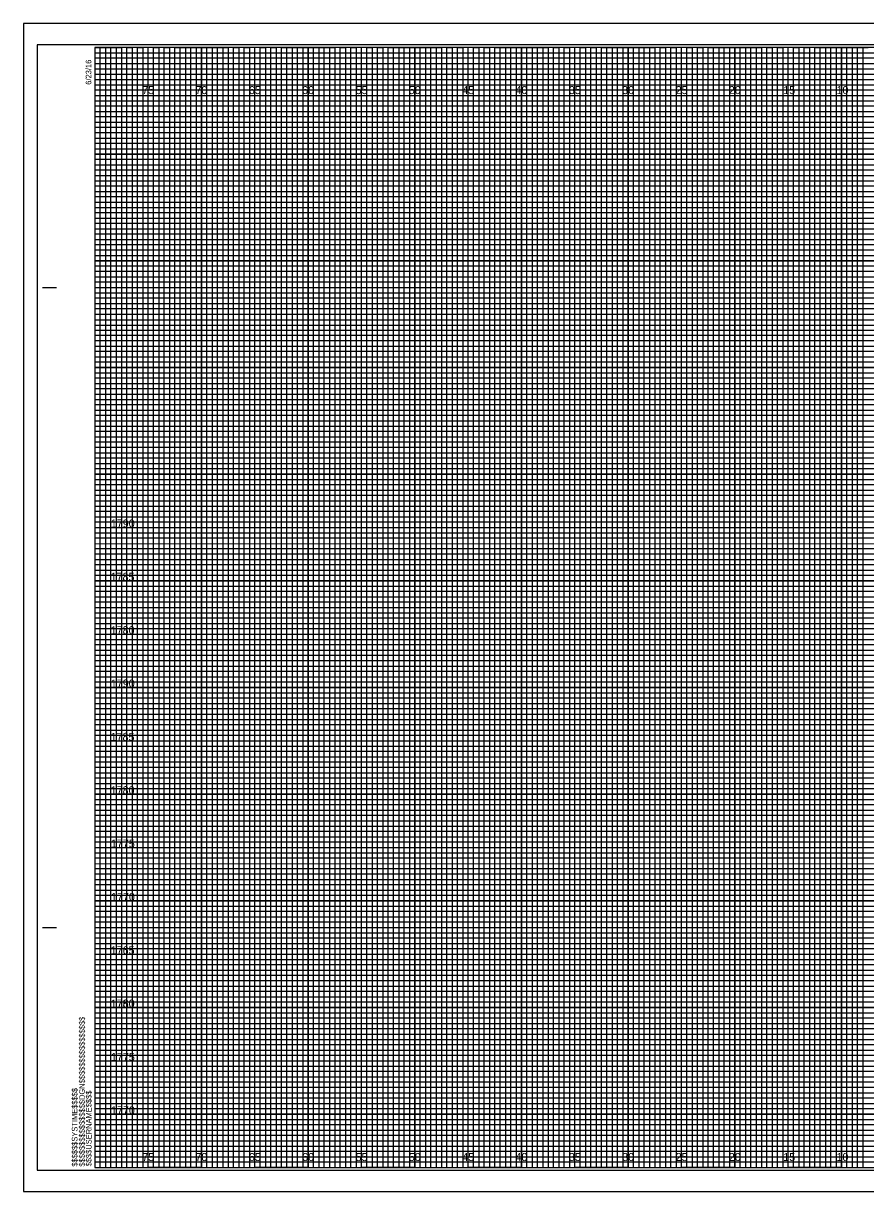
# Model space of a CAD drawing. Extents: x -7 to 162, y -2 to 107.
# Drawn here: x -6.7 to 72.2, y -2.3 to 107.3 of the extents above; entities that cross this region are included whole.
import ezdxf

# ---------------------------------------------------------------- set-up
doc = ezdxf.new("R2010")
doc.units = 0
for name, color, linetype in [('Prop XS Elevation Labels', 7, 'Continuous'), ('Prop XS Offset Labels', 7, 'Continuous'), ('Sheet Cross Section CELL', 7, 'Continuous'), ('Sheet Cross Section Grid Major CELL', 7, 'Continuous'), ('Sheet Cross Section Grid Middle CELL', 7, 'Continuous'), ('Sheet Cross Section Grid Minor 1 CELL', 7, 'Continuous'), ('Sheet Cross Section Grid Minor 2 CELL', 7, 'Continuous'), ('Sheet Cutting Line CELL', 7, 'Continuous'), ('Sheet DOT Grid CELL', 7, 'Continuous'), ('Sheet Plot Border Inside CELL', 7, 'Continuous'), ('Sheet Plot Border Outside CELL', 7, 'Continuous')]:
    doc.layers.add(name, color=color, linetype=linetype)

msp = doc.modelspace()

# ---------------------------------------------------------------- linework, layer by layer
at = {"layer": 'Sheet Cross Section CELL'}
for p, q in [((-4.9, 82.5), (-3.65, 82.5)), ((-4.85, 82.5), (-3.6, 82.5)), ((-4.9, 22.5), (-3.65, 22.5)), ((-4.85, 22.5), (-3.6, 22.5)), ((0, 0), (0, 0)), ((0, 0), (0, 0)), ((0, 0), (0, 0)), ((0, 0), (0, 0)), ((0, 0), (0, 0)), ((0, 0), (0, 0)), ((0, 0), (0, 0))]:
    msp.add_line(p, q, dxfattribs=at)
msp.add_lwpolyline([(160, 105), (0, 105), (0, 0), (160, 0)], close=True, dxfattribs=at)
at = {"layer": 'Sheet Cross Section Grid Major CELL'}
for p, q in [((5, 105), (0, 105)), ((5, 0), (5, 105)), ((15, 105), (10, 105)), ((10, 105), (10, 0)), ((15, 0), (15, 105)), ((25, 105), (20, 105)), ((20, 105), (20, 0)), ((25, 0), (25, 105)), ((35, 105), (30, 105)), ((30, 105), (30, 0)), ((35, 0), (35, 105)), ((45, 105), (40, 105)), ((40, 105), (40, 0)), ((45, 0), (45, 105)), ((55, 105), (50, 105)), ((50, 105), (50, 0)), ((55, 0), (55, 105)), ((65, 105), (60, 105)), ((60, 105), (60, 0)), ((65, 0), (65, 105)), ((75, 105), (70, 105)), ((70, 105), (70, 0)), ((10, 0), (5, 0)), ((20, 0), (15, 0)), ((30, 0), (25, 0)), ((40, 0), (35, 0)), ((50, 0), (45, 0)), ((60, 0), (55, 0)), ((70, 0), (65, 0))]:
    msp.add_line(p, q, dxfattribs=at)
for points in [[(0, 100), (160, 100), (160, 95), (0, 95)], [(0, 90), (160, 90), (160, 85), (0, 85)], [(0, 80), (160, 80), (160, 75), (0, 75)], [(0, 70), (160, 70), (160, 65), (0, 65)], [(0, 60), (160, 60), (160, 55), (0, 55)], [(0, 50), (160, 50), (160, 45), (0, 45)], [(0, 40), (160, 40), (160, 35), (0, 35)], [(0, 30), (160, 30), (160, 25), (0, 25)], [(0, 20), (160, 20), (160, 15), (0, 15)], [(0, 10), (160, 10), (160, 5), (0, 5)]]:
    msp.add_lwpolyline(points, dxfattribs=at)
at = {"layer": 'Sheet Cross Section Grid Middle CELL'}
for points in [[(0, 105), (2.5, 105), (2.5, 0), (7.5, 0), (7.5, 105), (12.5, 105), (12.5, 0), (17.5, 0), (17.5, 105), (22.5, 105), (22.5, 0), (27.5, 0), (27.5, 105), (32.5, 105), (32.5, 0), (37.5, 0), (37.5, 105), (42.5, 105), (42.5, 0), (47.5, 0), (47.5, 105), (52.5, 105), (52.5, 0), (57.5, 0), (57.5, 105), (62.5, 105), (62.5, 0), (67.5, 0), (67.5, 105), (72.5, 105)], [(0, 102.5), (137.5, 102.5)], [(0, 92.5), (160, 92.5), (160, 97.5), (0, 97.5)], [(0, 82.5), (160, 82.5), (160, 87.5), (0, 87.5)], [(0, 72.5), (160, 72.5), (160, 77.5), (0, 77.5)], [(0, 62.5), (160, 62.5), (160, 67.5), (0, 67.5)], [(0, 52.5), (160, 52.5), (160, 57.5), (0, 57.5)], [(0, 42.5), (160, 42.5), (160, 47.5), (0, 47.5)], [(0, 32.5), (160, 32.5), (160, 37.5), (0, 37.5)], [(0, 22.5), (160, 22.5), (160, 27.5), (0, 27.5)], [(0, 12.5), (160, 12.5), (160, 17.5), (0, 17.5)], [(0, 2.5), (160, 2.5), (160, 7.5), (0, 7.5)]]:
    msp.add_lwpolyline(points, dxfattribs=at)
at = {"layer": 'Sheet Cross Section Grid Minor 1 CELL'}
for p, q in [((0, 104.5), (130, 104.5)), ((130, 103.99), (0, 103.99)), ((0, 103.99), (0, 103.5)), ((0, 103.5), (130, 103.5)), ((130, 102.95), (0, 102.95)), ((0, 102.95), (0, 102)), ((0, 102), (160, 102))]:
    msp.add_line(p, q, dxfattribs=at)
for points in [[(0, 101.5), (135, 101.5), (160, 101.5), (160, 101), (0, 101)], [(0, 100.5), (160, 100.5), (160, 99.5), (0, 99.5)], [(0, 99), (160, 99), (160, 98.5), (0, 98.49)], [(0, 98), (160, 98), (160, 97), (0, 97)], [(0, 96.5), (160, 96.5), (160, 96), (0, 96)], [(0, 95.5), (160, 95.5), (160, 94.5), (0, 94.5)], [(0, 94), (160, 94), (160, 93.5), (0, 93.5)], [(0, 93), (160, 93), (160, 92), (0, 92)], [(0, 91.5), (160, 91.5), (160, 91), (0, 91)], [(0, 90.5), (160, 90.5), (160, 89.5), (0, 89.5)], [(0, 89), (160, 89), (160, 88.5), (0, 88.5)], [(0, 88), (160, 88), (160, 86.98), (160, 86.5), (160, 86), (0, 86)], [(0, 87), (160, 87), (160, 86.5), (0, 86.5)], [(0, 85.5), (160, 85.5), (160, 84.5), (0, 84.52)], [(0, 84.52), (160, 84.5), (160, 84), (0, 84)], [(0, 83.5), (160, 83.5), (160, 83), (0, 83)], [(0, 82), (160, 82), (160, 81.5), (0, 81.5)], [(0, 81), (160, 81), (160, 80.5), (0, 80.5)], [(-0.04, 79.45), (160, 79.45), (160, 78.94), (-0.04, 78.94)], [(0, 78.5), (160, 78.5), (160, 78), (0, 78)], [(0, 77), (160, 77), (160, 76.5), (0, 76.5)], [(0, 76), (160, 76), (160, 75.5), (0, 75.5)], [(0, 74.5), (160, 74.5), (160, 74), (0, 74)], [(0, 73.5), (160, 73.5), (160, 73), (0, 73)], [(0, 72), (160, 72), (160, 71.5), (0, 71.5)], [(0, 71), (160, 71), (160, 70.5), (0, 70.5)], [(0, 69.5), (160, 69.5), (160, 68.99), (0, 69)], [(0, 68.5), (160, 68.5), (160, 68), (0, 68)], [(0, 67), (160, 67), (160, 66.5), (0, 66.5)], [(0, 66), (160, 66), (160, 65.5), (0, 65.5)], [(0, 64.5), (160, 64.5), (160, 64), (0, 64)], [(0, 63.5), (160, 63.5), (160, 63), (0, 63)], [(0, 62), (160, 62), (160, 61.5), (0, 61.5)], [(0, 61), (160, 61), (160, 60.5), (0, 60.5)], [(0, 59.5), (160, 59.5), (160, 59), (0, 59)], [(0, 58.5), (160.03, 58.45), (160, 58), (0, 58)], [(0, 57), (160, 57), (160, 56.5), (0, 56.5)], [(0, 56), (160, 56), (160, 55.5), (0, 55.5)], [(0, 54.5), (160, 54.5), (160, 54), (0, 54)], [(0, 53.5), (160, 53.5), (160, 53), (0, 53)], [(0, 52), (160, 52), (160, 51.5), (0, 51.5)], [(0, 51), (160, 51), (160, 50.5), (0, 50.5)], [(0, 49.5), (160, 49.5), (160, 49), (0, 49)], [(0, 48.5), (160, 48.5), (160, 48), (0, 48)], [(0, 47), (160, 47), (160, 46.5), (0, 46.5)], [(0, 46), (160, 46), (160, 45.5), (0, 45.5)], [(0, 44.5), (160, 44.5), (160, 44), (0, 44)], [(0, 43.5), (160, 43.5), (160, 43), (0, 43)], [(0, 42), (160, 42), (160, 41.5), (0, 41.5)], [(0, 41), (160, 41), (160, 40.5), (0, 40.5)], [(0, 39.5), (160, 39.5), (160, 38.99), (0, 39)], [(0, 38.5), (160, 38.5), (160, 38), (0, 38)], [(0, 37), (160, 37), (160, 36.5), (0, 36.5)], [(0, 36), (160, 36), (160, 35.5), (0, 35.5)], [(0, 34.5), (160, 34.5), (160, 34), (0, 34)], [(0, 33.5), (160, 33.5), (160, 33), (0, 33)], [(0, 32), (160, 32), (160, 31.5), (0, 31.5)], [(0, 31), (160, 31), (160, 30.5), (0, 30.5)], [(0, 29.5), (160, 29.5), (160, 29), (0, 29)], [(0, 28.5), (160.03, 28.46), (160, 28), (0, 28)], [(0, 27), (160, 27), (160, 26.5), (0, 26.5)], [(0, 26), (160, 26), (160, 25.5), (0, 25.5)], [(0, 24.5), (160, 24.5), (160, 24), (0, 24)], [(0, 23.5), (160, 23.5), (160, 23), (0, 23)], [(0, 22), (160, 22), (160, 21.5), (0, 21.5)], [(0, 21), (160, 21), (160, 20.5), (0, 20.5)], [(0, 19.5), (160, 19.5), (160, 19), (0, 19)], [(0, 18.5), (160, 18.5), (160, 18), (0, 18)], [(0, 17), (160, 17), (160, 16.5), (0, 16.5)], [(0, 16), (160, 16), (160, 15.5), (0, 15.5)], [(0, 14.5), (160, 14.5), (160, 14), (0, 14)], [(0, 13.5), (160, 13.5), (160, 13), (0, 13)], [(0, 12), (160, 12), (160, 11.5), (0, 11.5)], [(0, 11), (160, 11), (160, 10.5), (0, 10.5)], [(0, 9.5), (160, 9.5), (160, 9), (0, 9)], [(0, 8.5), (160, 8.5), (160, 8), (0, 8)], [(0, 7), (160, 7), (160, 6.5), (0, 6.5)], [(0, 6), (160, 6), (160, 5.5), (0, 5.5)], [(0, 4.5), (160, 4.5), (160, 4), (0, 4)], [(0, 3.5), (160, 3.5), (160, 3), (0, 3)], [(0, 2), (160, 2), (160, 1.5), (0, 1.5)], [(0, 1), (160, 1), (160, 0.5), (0, 0.5)]]:
    msp.add_lwpolyline(points, dxfattribs=at)
at = {"layer": 'Sheet Cross Section Grid Minor 2 CELL'}
for points in [[(0, 0), (0.5, 0), (0.5, 105), (1, 105), (1, 0)], [(1, 0), (1.5, 0), (1.5, 105), (2, 105), (2, 0)], [(2.5, 0), (3, 0), (3, 105), (3.5, 105), (3.5, 0)], [(3.5, 0), (4, 0), (4, 105), (4.5, 105), (4.5, 0)], [(5, 0), (5.5, 0), (5.5, 105), (6, 105), (6, 0)], [(6, 0), (6.5, 0), (6.5, 105), (7, 105), (7, 0)], [(7.5, 0), (8, 0), (8, 105), (8.5, 105), (8.5, 0)], [(8.5, 0), (9, 0), (9, 105), (9.5, 105), (9.5, 0)], [(10, 0), (10.5, 0), (10.5, 105), (11, 105), (11, 0)], [(11, 0), (11.5, 0), (11.5, 105), (12, 105), (12, 0)], [(12.5, 0), (13, 0), (13, 105), (13.5, 105), (13.5, 0)], [(13.5, 0), (14, 0), (14, 105), (14.5, 105), (14.5, 0)], [(15, 0), (15.5, 0), (15.5, 105), (16, 105), (16, 0)], [(16, 0), (16.5, 0), (16.5, 105), (17, 105), (17, 0)], [(17.5, 0), (18, 0), (18, 105), (18.5, 105), (18.5, 0)], [(18.5, 0), (19, 0), (19, 105), (19.5, 105), (19.5, 0)], [(20, 0), (20.5, 0), (20.5, 105), (21, 105), (21, 0)], [(21, 0), (21.5, 0), (21.5, 105), (22, 105), (22, 0)], [(22.5, 0), (23, 0), (23, 105), (23.5, 105), (23.5, 0)], [(23.5, 0), (24, 0), (24, 105), (24.5, 105), (24.5, 0)], [(25, 0), (25.5, 0), (25.5, 105), (26, 105), (26, 0)], [(26, 0), (26.5, 0), (26.5, 105), (27, 105), (27, 0)], [(27.5, 0), (28, 0), (28, 105), (28.5, 105), (28.5, 0)], [(28.5, 0), (29, 0), (29, 105), (29.5, 105), (29.5, 0)], [(30, 0), (30.5, 0), (30.5, 105), (31, 105), (31, 0)], [(31, 0), (31.5, 0), (31.5, 105), (32, 105), (32, 0)], [(32.5, 0), (33, 0), (33, 105), (33.5, 105), (33.5, 0)], [(33.5, 0), (34, 0), (34, 105), (34.5, 105), (34.5, 0)], [(35, 0), (35.5, 0), (35.5, 105), (36, 105), (36, 0)], [(36, 0), (36.5, 0), (36.5, 105), (37, 105), (37, 0)], [(37.5, 0), (38, 0), (38, 105), (38.5, 105), (38.5, 0)], [(38.5, 0), (39, 0), (39, 105), (39.5, 105), (39.5, 0)], [(40, 0), (40.5, 0), (40.5, 105), (41, 105), (41, 0)], [(41, 0), (41.5, 0), (41.5, 105), (42, 105), (42, 0)], [(42.5, 0), (43, 0), (43, 105), (43.5, 105), (43.5, 0)], [(43.5, 0), (44, 0), (44, 105), (44.5, 105), (44.5, 0)], [(45, 0), (45.5, 0), (45.5, 105), (46, 105), (46, 0)], [(46, 0), (46.5, 0), (46.5, 105), (47, 105), (47, 0)], [(47.5, 0), (48, 0), (48, 105), (48.5, 105), (48.5, 0)], [(48.5, 0), (49, 0), (49, 105), (49.5, 105), (49.5, 0)], [(50, 0), (50.5, 0), (50.5, 105), (51, 105), (51, 0)], [(51, 0), (51.5, 0), (51.5, 105), (52, 105), (52, 0)], [(52.5, 0), (53, 0), (53, 105), (53.5, 105), (53.5, 0)], [(53.5, 0), (54, 0), (54, 105), (54.5, 105), (54.5, 0)], [(55, 0), (55.5, 0), (55.5, 105), (56, 105), (56, 0)], [(56, 0), (56.5, 0), (56.5, 105), (57, 105), (57, 0)], [(57.5, 0), (58, 0), (58, 105), (58.5, 105), (58.5, 0)], [(58.5, 0), (59, 0), (59, 105), (59.5, 105), (59.5, 0)], [(60, 0), (60.5, 0), (60.5, 105), (61, 105), (61, 0)], [(61, 0), (61.5, 0), (61.5, 105), (62, 105), (62, 0)], [(62.5, 0), (63, 0), (63, 105), (63.5, 105), (63.5, 0)], [(63.5, 0), (64, 0), (64, 105), (64.5, 105), (64.5, 0)], [(65, 0), (65.5, 0), (65.5, 105), (66, 105), (66, 0)], [(66, 0), (66.5, 0), (66.5, 105), (67, 105), (67, 0)], [(67.5, 0), (68, 0), (68, 105), (68.5, 105), (68.5, 0)], [(68.5, 0), (69, 0), (69, 105), (69.5, 105), (69.5, 0)], [(70, 0), (70.5, 0), (70.5, 105), (71, 105), (71, 0)], [(71, 0), (71.5, 0), (71.5, 105), (72, 105), (72, 0)]]:
    msp.add_lwpolyline(points, dxfattribs=at)
at = {"layer": 'Sheet Cutting Line CELL'}
for p, q in [((161.65, 107.25), (-6.7, 107.25)), ((-6.7, 107.25), (-6.7, -2.25)), ((-6.7, -2.25), (161.65, -2.25))]:
    msp.add_line(p, q, dxfattribs=at)
at = {"layer": 'Sheet DOT Grid CELL'}
for p, q in [((5, 0), (5, 105)), ((10, 0), (10, 105)), ((15, 0), (15, 105)), ((20, 0), (20, 105)), ((25, 0), (25, 105)), ((30, 0), (30, 105)), ((35, 0), (35, 105)), ((40, 0), (40, 105)), ((45, 0), (45, 105)), ((50, 0), (50, 105)), ((55, 0), (55, 105)), ((60, 0), (60, 105)), ((65, 0), (65, 105)), ((70, 0), (70, 105)), ((0, 100), (160, 100)), ((0, 95), (160, 95)), ((0, 90), (160, 90)), ((0, 85), (160, 85)), ((0, 80), (160, 80)), ((0, 75), (160, 75)), ((0, 70), (160, 70)), ((0, 65), (160, 65)), ((0, 60), (160, 60)), ((0, 55), (160, 55)), ((0, 50), (160, 50)), ((0, 45), (160, 45)), ((0, 40), (160, 40)), ((0, 35), (160, 35)), ((0, 30), (160, 30)), ((0, 25), (160, 25)), ((0, 20), (160, 20)), ((0, 15), (160, 15)), ((0, 10), (160, 10)), ((0, 5), (160, 5))]:
    msp.add_line(p, q, dxfattribs=at)
at = {"layer": 'Sheet Plot Border Inside CELL'}
msp.add_lwpolyline([(-5.4, -0.25), (161.2, -0.25), (161.2, 105.25), (-5.4, 105.25)], close=True, dxfattribs=at)
at = {"layer": 'Sheet Plot Border Outside CELL'}
msp.add_lwpolyline([(-6.7, -2.25), (161.65, -2.25), (161.65, 107.25), (-6.7, 107.25)], close=True, dxfattribs=at)

# ---------------------------------------------------------------- texts
at = {"layer": 'Prop XS Elevation Labels'}
for s, p in [('1790', (1.5, 60)), ('1785', (1.48, 55)), ('1780', (1.49, 50)), ('1790', (1.5, 45)), ('1785', (1.48, 40)), ('1780', (1.49, 35)), ('1775', (1.51, 30)), ('1770', (1.52, 25)), ('1765', (1.49, 20)), ('1780', (1.49, 15)), ('1760', (1.5, 15)), ('1775', (1.51, 10)), ('1770', (1.52, 5))]:
    msp.add_text(s, height=0.75, dxfattribs=at).set_placement(p)
at = {"layer": 'Prop XS Offset Labels'}
for s, p in [('75', (4.44, 100.62)), ('70', (9.43, 100.62)), ('65', (14.44, 100.62)), ('60', (19.43, 100.62)), ('55', (24.44, 100.62)), ('50', (29.43, 100.62)), ('45', (34.44, 100.62)), ('40', (39.43, 100.62)), ('35', (44.44, 100.62)), ('30', (49.43, 100.62)), ('25', (54.44, 100.62)), ('20', (59.43, 100.62)), ('15', (64.53, 100.62)), ('10', (69.52, 100.62)), ('75', (4.44, 0.62)), ('70', (9.43, 0.62)), ('65', (14.44, 0.62)), ('60', (19.43, 0.62)), ('55', (24.44, 0.62)), ('50', (29.43, 0.62)), ('45', (34.44, 0.62)), ('40', (39.43, 0.62)), ('35', (44.44, 0.62)), ('30', (49.43, 0.62)), ('25', (54.44, 0.62)), ('20', (59.43, 0.62)), ('15', (64.53, 0.62)), ('10', (69.52, 0.62))]:
    msp.add_text(s, height=0.75, dxfattribs=at).set_placement(p)
at = {"layer": 'Sheet Cross Section CELL'}
for s, p in [('6/23/16', (-0.33, 101.5)), ('$$$$$$$$$$$$$$$$DGN$$$$$$$$$$$$$$$$', (-0.94, 0.09)), ('$$$$$$SYSTIME$$$$$', (-1.63, 0.09)), ('$$$$USERNAME$$$$', (-0.31, 0.12))]:
    msp.add_text(s, height=0.525, rotation=90, dxfattribs=at).set_placement(p)

doc.saveas('drawing.dxf')
